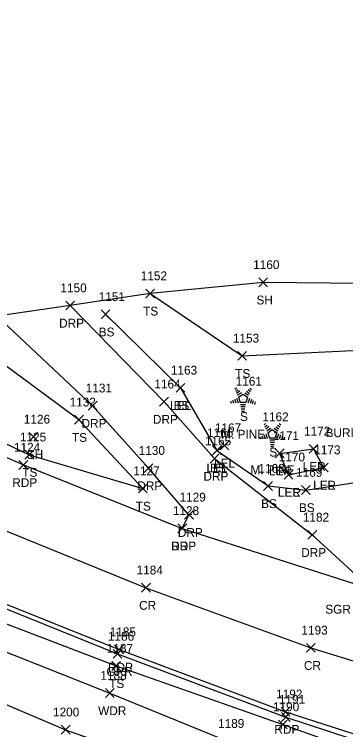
# Model space of a CAD drawing. Extents: x 1547013 to 1549434, y 267998 to 268739.
# Drawn here: x 1548467.5 to 1548542.6, y 268107.9 to 268269.9 of the extents above; entities that cross this region are included whole.
import ezdxf

# ---------------------------------------------------------------- set-up
doc = ezdxf.new("R2010")
doc.units = 0
for name, color, linetype in [('L_A', 7, 'Continuous'), ('L_C', 7, 'Continuous'), ('L_I', 7, 'Continuous'), ('L_TIC', 7, 'Continuous'), ('LARO', 7, 'Continuous'), ('LAWA', 7, 'Continuous'), ('LELB', 7, 'Continuous'), ('LSOGP', 7, 'Continuous'), ('LTC', 7, 'Continuous'), ('P_A', 7, 'Continuous'), ('P_I', 7, 'Continuous'), ('P_TIC', 7, 'Continuous'), ('PET', 7, 'Continuous'), ('PRC', 7, 'Continuous'), ('R_A', 7, 'Continuous'), ('R_C', 7, 'Continuous'), ('R_I', 7, 'Continuous'), ('R_TIC', 7, 'Continuous'), ('RDP', 7, 'Continuous'), ('RGR', 7, 'Continuous'), ('U_C', 7, 'Continuous')]:
    doc.layers.add(name, color=color, linetype=linetype)

msp = doc.modelspace()

# ---------------------------------------------------------------- linework, layer by layer
at = {"layer": 'L_TIC'}
for points in [[(1548522.9, 268208.23), (1548524.9, 268210.23)], [(1548524.9, 268208.23), (1548522.9, 268210.23)], [(1548497.29, 268205.72), (1548499.29, 268207.72)], [(1548499.29, 268205.72), (1548497.29, 268207.72)], [(1548487.19, 268200.99), (1548489.19, 268202.99)], [(1548489.19, 268200.99), (1548487.19, 268202.99)], [(1548518.16, 268191.59), (1548520.16, 268193.59)], [(1548520.16, 268191.59), (1548518.16, 268193.59)], [(1548504.17, 268184.35), (1548506.17, 268186.35)], [(1548506.17, 268184.35), (1548504.17, 268186.35)], [(1548504.17, 268184.35), (1548506.17, 268186.35)], [(1548506.17, 268184.35), (1548504.17, 268186.35)], [(1548481.16, 268177.12), (1548483.16, 268179.12)], [(1548483.16, 268177.12), (1548481.16, 268179.12)], [(1548470.85, 268173.25), (1548472.85, 268175.25)], [(1548472.85, 268173.25), (1548470.85, 268175.25)], [(1548514.14, 268171.29), (1548516.14, 268173.29)], [(1548516.14, 268171.29), (1548514.14, 268173.29)], [(1548534.29, 268170.55), (1548536.29, 268172.55)], [(1548536.29, 268170.55), (1548534.29, 268172.55)], [(1548469.91, 268169.21), (1548471.91, 268171.21)], [(1548471.91, 268169.21), (1548469.91, 268171.21)], [(1548512.43, 268170.19), (1548514.43, 268172.19)], [(1548514.43, 268170.19), (1548512.43, 268172.19)], [(1548512.43, 268170.19), (1548514.43, 268172.19)], [(1548514.43, 268170.19), (1548512.43, 268172.19)], [(1548526.64, 268169.51), (1548528.64, 268171.51)], [(1548528.64, 268169.51), (1548526.64, 268171.51)], [(1548536.6, 268166.3), (1548538.6, 268168.3)], [(1548538.6, 268166.3), (1548536.6, 268168.3)], [(1548536.6, 268166.3), (1548538.6, 268168.3)], [(1548538.6, 268166.3), (1548536.6, 268168.3)], [(1548528.64, 268164.68), (1548530.64, 268166.68)], [(1548530.64, 268164.68), (1548528.64, 268166.68)], [(1548528.64, 268164.68), (1548530.64, 268166.68)], [(1548530.64, 268164.68), (1548528.64, 268166.68)], [(1548495.62, 268161.55), (1548497.62, 268163.55)], [(1548497.62, 268161.55), (1548495.62, 268163.55)], [(1548524, 268162.12), (1548526, 268164.12)], [(1548526, 268162.12), (1548524, 268164.12)], [(1548532.55, 268161.21), (1548534.55, 268163.21)], [(1548534.55, 268161.21), (1548532.55, 268163.21)], [(1548489.6, 268121.37), (1548491.6, 268123.37)], [(1548491.6, 268121.37), (1548489.6, 268123.37)], [(1548488.15, 268115.23), (1548490.15, 268117.23)], [(1548490.15, 268115.23), (1548488.15, 268117.23)], [(1548527.34, 268108.13), (1548529.34, 268110.13)], [(1548529.34, 268108.13), (1548527.34, 268110.13)], [(1548478.13, 268106.94), (1548480.13, 268108.94)], [(1548480.13, 268106.94), (1548478.13, 268108.94)]]:
    msp.add_lwpolyline(points, dxfattribs=at)
at = {"layer": 'LARO'}
for points in [[(1548505.17, 268185.35), (1548513.43, 268171.19), (1548515.14, 268172.29)], [(1548529.64, 268165.68), (1548527.64, 268170.51), (1548535.29, 268171.55), (1548537.6, 268167.3)], [(1548529.64, 268165.68), (1548537.6, 268167.3)]]:
    msp.add_lwpolyline(points, dxfattribs=at)
at = {"layer": 'LAWA'}
msp.add_lwpolyline([(1548421.13, 268144.61), (1548456.38, 268129.21), (1548489.15, 268116.23), (1548515.82, 268105.35), (1548565.81, 268089.46), (1548595.41, 268078.87)], dxfattribs=at)
at = {"layer": 'LELB'}
for points in [[(1548293.13, 268254.53), (1548332.25, 268235.07), (1548368.2, 268219.22), (1548398.43, 268204.17), (1548432.39, 268188.56), (1548470.91, 268170.21), (1548496.62, 268162.55), (1548482.16, 268178.12), (1548462.07, 268192.9), (1548441.51, 268207.34), (1548411.84, 268225.63), (1548370.54, 268246.3), (1548337.89, 268260.04)], [(1548272.57, 268212.48), (1548289.14, 268210.26), (1548307.62, 268202.44), (1548323.1, 268196.35), (1548369.71, 268173.31), (1548388.46, 268161.7), (1548422.32, 268150.28), (1548459.33, 268134.33), (1548490.6, 268122.37), (1548528.34, 268109.13), (1548567.41, 268095.24), (1548592.2, 268086.56), (1548606.66, 268079.82), (1548620.32, 268072.15), (1548638.75, 268065.65), (1548644.4, 268061.61), (1548647.64, 268052.81), (1548649.6, 268041.05)], [(1548498.29, 268206.72), (1548519.16, 268192.59), (1548545.82, 268193.85), (1548579.38, 268191.11)], [(1548488.19, 268201.99), (1548505.17, 268185.35)], [(1548306.43, 268199.29), (1548321.43, 268192.43), (1548332.78, 268181.9), (1548367.71, 268165.7), (1548391.94, 268148.16), (1548415.52, 268137.54), (1548452.83, 268119.09), (1548479.13, 268107.94), (1548530.85, 268089.69)], [(1548513.43, 268171.19), (1548525, 268163.12), (1548533.55, 268162.21), (1548557.31, 268165.9), (1548576.5, 268161.35)]]:
    msp.add_lwpolyline(points, dxfattribs=at)
at = {"layer": 'LSOGP'}
msp.add_lwpolyline([(1548691.82, 268155.29), (1548664.24, 268170.51), (1548654.95, 268173.75), (1548643.15, 268190.11), (1548641.1, 268197.23), (1548631.96, 268206.47), (1548600.72, 268220.15), (1548585.67, 268217.81), (1548576.37, 268223.8), (1548554.2, 268208.91), (1548523.9, 268209.23), (1548498.29, 268206.72), (1548480.17, 268203.98), (1548463.54, 268201.58)], dxfattribs=at)
at = {"layer": 'LTC'}
for p, q in [((1548517.47, 268185.05), (1548517.83, 268185.31)), ((1548517.68, 268184.59), (1548518.21, 268184.97)), ((1548517.89, 268184.12), (1548518.59, 268184.63)), ((1548518.1, 268183.66), (1548518.98, 268184.29)), ((1548518.32, 268183.2), (1548519.34, 268183.93)), ((1548519.34, 268183.93), (1548520.33, 268183.21)), ((1548519.76, 268184.25), (1548520.57, 268183.66)), ((1548520.13, 268184.6), (1548520.81, 268184.1)), ((1548520.5, 268184.94), (1548521.05, 268184.55)), ((1548520.87, 268185.29), (1548521.29, 268184.99)), ((1548516.5, 268182.33), (1548516.66, 268181.86)), ((1548516.96, 268182.55), (1548517.17, 268181.9)), ((1548517.41, 268182.76), (1548517.69, 268181.93)), ((1548517.87, 268182.98), (1548518.2, 268181.96)), ((1548518.32, 268183.2), (1548518.71, 268182.01)), ((1548520.33, 268183.21), (1548519.94, 268182.01)), ((1548520.77, 268182.94), (1548520.43, 268181.9)), ((1548521.22, 268182.69), (1548520.93, 268181.8)), ((1548521.66, 268182.44), (1548521.42, 268181.71)), ((1548519.94, 268182.01), (1548518.71, 268182.01)), ((1548519.9, 268181.51), (1548518.76, 268181.51)), ((1548519.82, 268181.01), (1548518.83, 268181.01)), ((1548522.1, 268182.19), (1548521.92, 268181.61)), ((1548519.74, 268180.51), (1548518.9, 268180.51)), ((1548519.65, 268180.01), (1548518.98, 268180.01)), ((1548524.1, 268177), (1548524.46, 268177.26)), ((1548524.31, 268176.54), (1548524.84, 268176.92)), ((1548524.52, 268176.07), (1548525.22, 268176.58)), ((1548524.73, 268175.6), (1548525.61, 268176.24)), ((1548524.96, 268175.15), (1548525.97, 268175.88)), ((1548525.97, 268175.88), (1548526.96, 268175.16)), ((1548526.39, 268176.2), (1548527.2, 268175.61)), ((1548526.76, 268176.54), (1548527.44, 268176.05)), ((1548527.13, 268176.89), (1548527.68, 268176.49)), ((1548527.5, 268177.24), (1548527.92, 268176.94)), ((1548523.13, 268174.28), (1548523.29, 268173.81)), ((1548523.59, 268174.5), (1548523.8, 268173.85)), ((1548524.05, 268174.71), (1548524.32, 268173.88)), ((1548524.5, 268174.93), (1548524.83, 268173.91)), ((1548524.96, 268175.15), (1548525.34, 268173.96)), ((1548526.96, 268175.16), (1548526.57, 268173.96)), ((1548527.4, 268174.89), (1548527.06, 268173.85)), ((1548527.85, 268174.64), (1548527.56, 268173.75)), ((1548528.29, 268174.39), (1548528.05, 268173.66)), ((1548526.57, 268173.96), (1548525.34, 268173.96)), ((1548526.53, 268173.46), (1548525.39, 268173.46)), ((1548526.45, 268172.96), (1548525.46, 268172.96)), ((1548528.73, 268174.14), (1548528.55, 268173.56)), ((1548526.37, 268172.46), (1548525.54, 268172.46)), ((1548526.28, 268171.96), (1548525.61, 268171.96))]:
    msp.add_line(p, q, dxfattribs=at)
at = {"layer": 'P_TIC'}
for points in [[(1548468.56, 268166.88), (1548470.56, 268168.88)], [(1548470.56, 268166.88), (1548468.56, 268168.88)], [(1548504.57, 268152.53), (1548506.57, 268154.53)], [(1548506.57, 268152.53), (1548504.57, 268154.53)], [(1548496.35, 268139.09), (1548498.35, 268141.09)], [(1548498.35, 268139.09), (1548496.35, 268141.09)], [(1548533.69, 268125.49), (1548535.69, 268127.49)], [(1548535.69, 268125.49), (1548533.69, 268127.49)], [(1548490.25, 268125.1), (1548492.25, 268127.1)], [(1548492.25, 268125.1), (1548490.25, 268127.1)], [(1548527.96, 268111.02), (1548529.96, 268113.02)], [(1548529.96, 268111.02), (1548527.96, 268113.02)]]:
    msp.add_lwpolyline(points, dxfattribs=at)
at = {"layer": 'PET'}
for points in [[(1548291.29, 268251.79), (1548331.75, 268232.06), (1548365.57, 268215.99), (1548397.04, 268199.92), (1548430.53, 268185.01), (1548469.56, 268167.88), (1548505.57, 268153.53), (1548548.45, 268139.73), (1548572.84, 268130.65), (1548596.65, 268123.57), (1548616.57, 268118.19), (1548655.34, 268109.04), (1548680.93, 268103.12), (1548700.8, 268099.76), (1548753.55, 268092.31), (1548788.11, 268088.53), (1548842.08, 268084.26), (1548868.98, 268083.24)], [(1548277.31, 268222.58), (1548324.08, 268200.05), (1548370.89, 268177.56), (1548421.34, 268155.12), (1548457.66, 268139.55), (1548491.25, 268126.1), (1548528.96, 268112.02), (1548568.2, 268099.41), (1548604.28, 268089.49), (1548621.9, 268083.87), (1548638.12, 268079.83), (1548660.94, 268075.04), (1548683.04, 268070.81), (1548718.59, 268065.27), (1548750.02, 268060.75), (1548786.09, 268057.26), (1548818, 268054.36), (1548866.14, 268051.84)]]:
    msp.add_lwpolyline(points, dxfattribs=at)
at = {"layer": 'PRC'}
msp.add_lwpolyline([(1548285.23, 268237.15), (1548330.43, 268214.75), (1548376.37, 268192.58), (1548426.54, 268169.59), (1548464.29, 268153.5), (1548497.35, 268140.09), (1548534.69, 268126.49), (1548572.93, 268114.69), (1548608.02, 268104.77), (1548637.81, 268097.38), (1548663.07, 268091.69), (1548686.38, 268086.96), (1548723.69, 268081.05), (1548751.9, 268076.9), (1548786.74, 268073.36), (1548818.76, 268070.54), (1548866.8, 268068.08)], dxfattribs=at)
at = {"layer": 'R_TIC'}
for points in [[(1548479.17, 268202.98), (1548481.17, 268204.98)], [(1548481.17, 268202.98), (1548479.17, 268204.98)], [(1548484.25, 268180.3), (1548486.25, 268182.3)], [(1548486.25, 268180.3), (1548484.25, 268182.3)], [(1548500.43, 268181.21), (1548502.43, 268183.21)], [(1548502.43, 268181.21), (1548500.43, 268183.21)], [(1548511.88, 268168.31), (1548513.88, 268170.31)], [(1548513.88, 268168.31), (1548511.88, 268170.31)], [(1548496.9, 268166.16), (1548498.9, 268168.16)], [(1548498.9, 268166.16), (1548496.9, 268168.16)], [(1548506.08, 268155.6), (1548508.08, 268157.6)], [(1548508.08, 268155.6), (1548506.08, 268157.6)], [(1548504.57, 268152.53), (1548506.57, 268154.53)], [(1548506.57, 268152.53), (1548504.57, 268154.53)], [(1548534.03, 268151.05), (1548536.03, 268153.05)], [(1548536.03, 268151.05), (1548534.03, 268153.05)], [(1548489.9, 268124.1), (1548491.9, 268126.1)], [(1548491.9, 268124.1), (1548489.9, 268126.1)], [(1548528.02, 268109.81), (1548530.02, 268111.81)], [(1548530.02, 268109.81), (1548528.02, 268111.81)]]:
    msp.add_lwpolyline(points, dxfattribs=at)
at = {"layer": 'RDP'}
for points in [[(1548505.57, 268153.53), (1548507.08, 268156.6), (1548497.9, 268167.16), (1548485.25, 268181.3), (1548463.54, 268201.58), (1548445.25, 268213.44), (1548411.31, 268232.42), (1548374.18, 268251.32), (1548341.68, 268269.92)], [(1548480.17, 268203.98), (1548501.43, 268182.21), (1548512.88, 268169.31), (1548535.03, 268152.05), (1548548.45, 268139.73)]]:
    msp.add_lwpolyline(points, dxfattribs=at)
at = {"layer": 'RGR'}
msp.add_lwpolyline([(1548388.8, 268165.09), (1548420.43, 268153.83), (1548460.75, 268137.25), (1548490.9, 268125.1), (1548529.02, 268110.81), (1548568.38, 268097.87), (1548602.59, 268086.19)], dxfattribs=at)

# ---------------------------------------------------------------- texts
at = {"layer": 'L_A'}
for s, p in [('SH', (1548522.38, 268204.23)), ('TS', (1548496.7, 268201.72)), ('BS', (1548486.63, 268196.99)), ('TS', (1548517.57, 268187.59)), ('LEL', (1548502.8, 268180.35)), ('BS', (1548503.61, 268180.35)), ('S', (1548518.66, 268177.84)), ('TS', (1548480.57, 268173.12)), ('SH', (1548470.34, 268169.25)), ('S', (1548525.29, 268169.79)), ('LEL', (1548511.06, 268166.19)), ('BS', (1548511.87, 268166.19)), ('LEL', (1548512.78, 268167.29)), ('LER', (1548532.87, 268166.55)), ('TS', (1548469.32, 268165.21)), ('LER', (1548525.22, 268165.51)), ('LER', (1548535.19, 268162.3)), ('LEL', (1548535.24, 268162.3)), ('LER', (1548527.23, 268160.68)), ('LEL', (1548527.28, 268160.68)), ('TS', (1548495.03, 268157.55)), ('BS', (1548523.44, 268158.12)), ('BS', (1548532, 268157.21)), ('TS', (1548489.01, 268117.37)), ('WDR', (1548486.51, 268111.23))]:
    msp.add_text(s, height=2, dxfattribs=at).set_placement(p)
at = {"layer": 'L_C'}
for p in [(1548514.39, 268173.84), (1548521.03, 268165.79)]:
    msp.add_text('M. PINE', height=2, dxfattribs=at).set_placement(p)
at = {"layer": 'L_I'}
for s, p in [('1160', (1548521.64, 268212.23)), ('1152', (1548496.16, 268209.72)), ('1151', (1548486.63, 268204.99)), ('1153', (1548517.04, 268195.59)), ('1163', (1548502.99, 268188.35)), ('1163', (1548502.99, 268188.35)), ('1161', (1548517.67, 268185.84)), ('1132', (1548480.04, 268181.12)), ('1126', (1548469.67, 268177.25)), ('1162', (1548523.73, 268177.79)), ('1166', (1548511.2, 268174.19)), ('1166', (1548511.2, 268174.19)), ('1167', (1548512.96, 268175.29)), ('1172', (1548533.16, 268174.55)), ('1125', (1548468.78, 268173.21)), ('1171', (1548526.08, 268173.51)), ('1173', (1548535.48, 268170.3)), ('1173', (1548535.48, 268170.3)), ('1170', (1548527.43, 268168.68)), ('1170', (1548527.43, 268168.68)), ('1168', (1548522.82, 268166.12)), ('1127', (1548494.49, 268165.55)), ('1169', (1548531.37, 268165.21)), ('1187', (1548488.47, 268125.37)), ('1188', (1548487.02, 268119.23)), ('1200', (1548476.28, 268110.94)), ('1190', (1548526.12, 268112.13)), ('1189', (1548513.68, 268108.35))]:
    msp.add_text(s, height=2, dxfattribs=at).set_placement(p)
at = {"layer": 'LTC'}
for p in [(1548519.22, 268182.95), (1548525.85, 268174.9)]:
    msp.add_text('.', height=1.04, rotation=270, dxfattribs=at).set_placement(p)
at = {"layer": 'P_A'}
for s, p in [('RDP', (1548467.05, 268162.88)), ('RDP', (1548503.06, 268148.53)), ('CR', (1548495.78, 268135.09)), ('RDP', (1548488.74, 268121.1)), ('CR', (1548533.13, 268121.49)), ('RDP', (1548526.45, 268107.02))]:
    msp.add_text(s, height=2, dxfattribs=at).set_placement(p)
at = {"layer": 'P_I'}
for s, p in [('1124', (1548467.43, 268170.88)), ('1128', (1548503.44, 268156.53)), ('1184', (1548495.22, 268143.09)), ('1185', (1548489.13, 268129.1)), ('1193', (1548532.57, 268129.49)), ('1192', (1548526.84, 268115.02))]:
    msp.add_text(s, height=2, dxfattribs=at).set_placement(p)
at = {"layer": 'R_A'}
for s, p in [('DRP', (1548477.66, 268198.98)), ('DRP', (1548498.92, 268177.21)), ('DRP', (1548482.74, 268176.3)), ('DRP', (1548510.37, 268164.31)), ('DRP', (1548495.39, 268162.16)), ('DRP', (1548504.57, 268151.6)), ('DRP', (1548503.06, 268148.53)), ('DRP', (1548532.52, 268147.05)), ('GRR', (1548488.39, 268120.1))]:
    msp.add_text(s, height=2, dxfattribs=at).set_placement(p)
at = {"layer": 'R_C'}
msp.add_text('SGR W/STEEL POSTS', height=2, dxfattribs=at).set_placement((1548537.98, 268134.21))
at = {"layer": 'R_I'}
for s, p in [('1150', (1548477.96, 268206.98)), ('1164', (1548499.25, 268185.21)), ('1131', (1548483.69, 268184.3)), ('1165', (1548510.7, 268172.31)), ('1130', (1548495.69, 268170.16)), ('1129', (1548504.95, 268159.6)), ('1128', (1548503.44, 268156.53)), ('1182', (1548532.9, 268155.05)), ('1186', (1548488.72, 268128.1)), ('1191', (1548527.46, 268113.81))]:
    msp.add_text(s, height=2, dxfattribs=at).set_placement(p)
at = {"layer": 'U_C'}
msp.add_text('BURIED PROPANE TANK', height=2, dxfattribs=at).set_placement((1548538.05, 268174.18))

doc.saveas('drawing.dxf')
